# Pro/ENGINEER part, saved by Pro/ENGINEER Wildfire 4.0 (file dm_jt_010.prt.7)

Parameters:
  METRIC = "NO"

Other parameters: PITCH, DRILL_POINT_ANGLE, DRILL_DEPTH, DRILL_DIAMETER, THREAD_DIAMETER, THREADS_PER_INCH, THREAD_DEPTH, THREAD_LENGTH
